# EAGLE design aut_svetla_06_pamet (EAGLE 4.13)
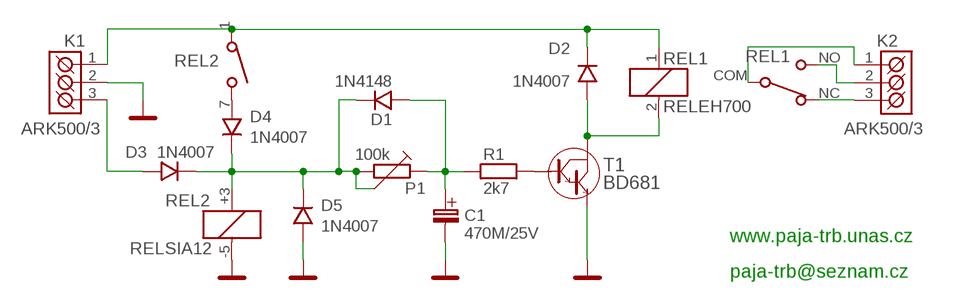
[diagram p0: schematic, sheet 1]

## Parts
C1  470M/25V  [C_EL_5]
D1  1N4148  1N4148_SMD_SOD80  [SOD-80]
D2  1N4007  1N4007_SMD_SM-1  [SM-1]
D3  1N4007  1N4007_SMD_SM-1  [SM-1]
D4  1N4007  1N4007_SMD_SM-1  [SM-1]
D5  1N4007  1N4007_SMD_SM-1  [SM-1]
K1  ARK500/3  [ARK500/3]
K2  ARK500/3  [ARK500/3]
P1  100k  PT-6_V-LEZ  [PT6V]
R1  2k7  R_SMD_1206  [1206]
REL1  RELEH700  [RELEH700]
REL2  RELSIA12  RELSIA  [RELSIA]
T1  BD681  BD681_STOJ  [TO-126S]

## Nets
GND: C1.C-(C_EL-) D5.A K1.2(K2) REL2.-5(CIVKA:C-) T1.1(E)
N$1: D2.K K1.1(K1) REL1.1(CIVKA:C1) REL2.1
N$2: C1.C+(C_EL+) D1.A P1.1 R1.1
N$3: D2.A REL1.2(CIVKA:C2) T1.2(C)
N$4: K2.2(K2) REL1.NO(PREP:NO)
N$5: K2.3(K3) REL1.NC(PREP:NC)
N$6: K2.1(K1) REL1.COM(PREP:COM)
N$7: R1.2 T1.3(B)
N$8: D4.A REL2.7
N$9: D1.K D3.K D4.K D5.K P1.2 P1.3 REL2.+3(CIVKA:C+)
N$10: D3.A K1.3(K3)

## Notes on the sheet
- www.paja-trb.unas.cz
- paja-trb@seznam.cz

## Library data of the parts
C1 = #PaJa_C-el:470M/25V
D1 = #PaJa_17:1N4148: Univerzalni dioda - 0,15A, 75V
D2 = #PaJa_17:1N4007: Usmernovaci dioda - 1A, 1000V
D3-D5 = #PaJa_18:1N4007: Usmernovaci dioda - 1A, 1000V
K1 K2 = #PaJa_17:ARK500/3: Svorkovnice - roztec 5mm - trojita
P1 = #PaJa_18:PT-6: Trimr PT6 - 6,3mm
R1 = #PaJa_17:R: Rezistor
REL1 = #PaJa_18:RELEH700
REL2 = #PaJa_18:RELSIA??: RELE - 1x spinaci, 5V, 12V, 24V max. spinany proud = 0,5A
T1 = #PaJa_17:BD681

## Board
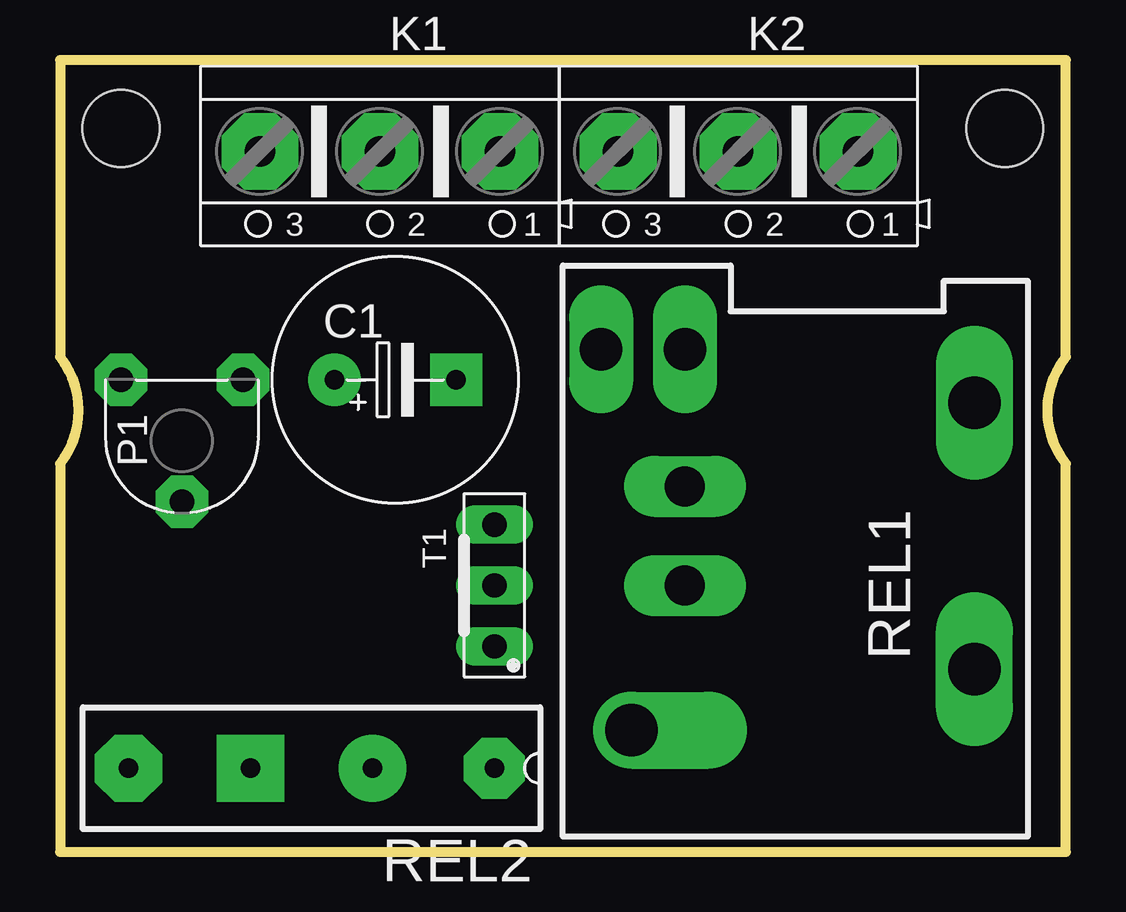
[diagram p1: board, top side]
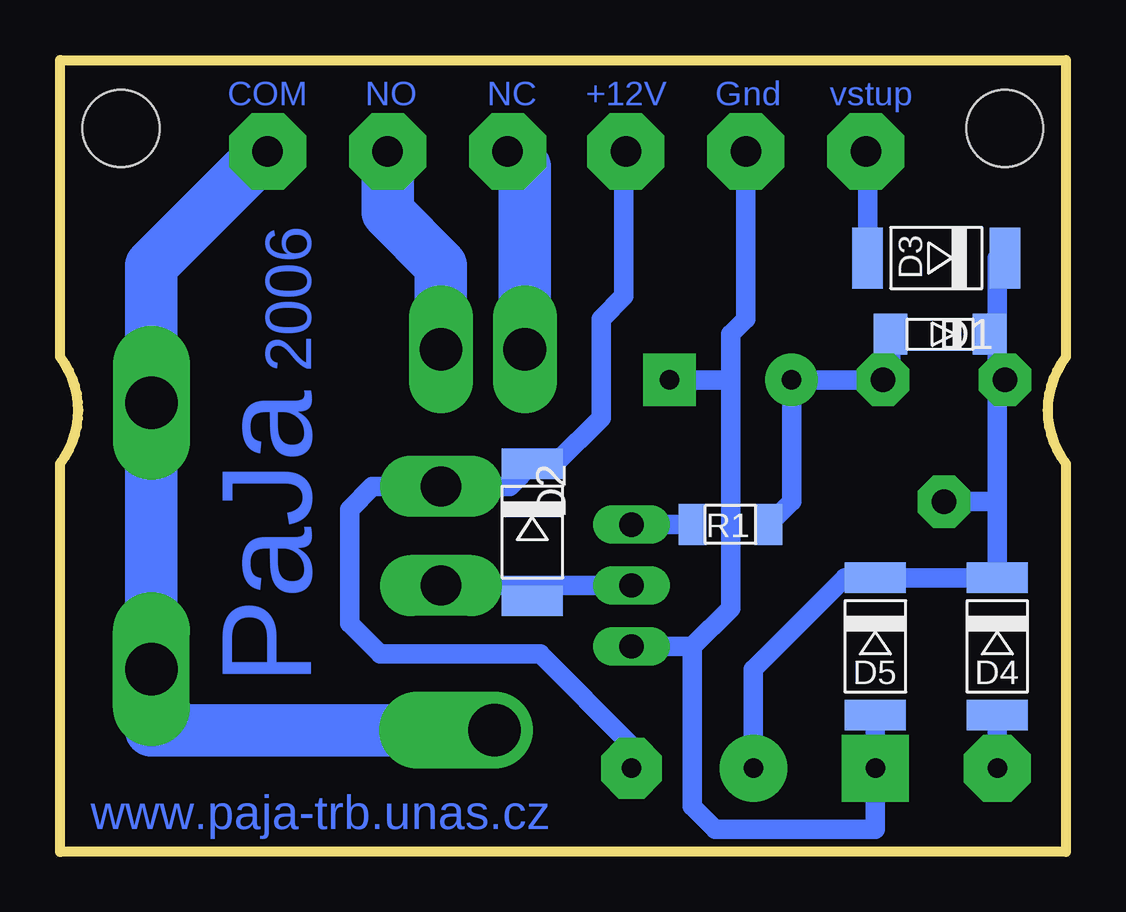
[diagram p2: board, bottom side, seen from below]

Size 41.91 x 33.02 mm. Coordinates in mm from the lower left corner, seen from the top.
Outline: 41.9,0 0,0 0,16.19 arc76 0,20.64 0,33.01 41.9,33.01
Outline: 41.91,0 41.91,16.19 arc-76 41.91,20.64 41.91,33.02
Copper layers (1*16): Top 0.035mm / dielectric 1.5mm / Bottom 0.035mm
Design rules "default": minimum track width 10mil, minimum drill 24mil, track to track 8mil, track to pad 8mil, pad to pad 8mil, via to via 8mil, smd to smd 8mil, copper to edge 40mil, drill to drill 8mil, minimum pad ring 10mil, minimum via ring 8mil, stop-mask expansion 4mil, vias tented up to drill 0mil, thermal gap 10mil
Holes 3.2 mm at 2.54,30.16 39.37,30.16

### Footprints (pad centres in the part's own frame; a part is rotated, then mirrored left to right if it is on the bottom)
C_EL_5 = drill 0.813 pad 2.184 round: C+ -2.54,0 | drill 0.813 pad 2.184 square: C- 2.54,0
SOD-80 = smd 1.397 x 1.702: A 1.905,0; K -2.223,0
SM-1 = smd 1.27 x 2.54: A 2.54,0; K -3.175,0
ARK500/3 = drill 1.27 pad 3.2 octagon: 1 -5,0; 2 0,0; 3 5,0
PT6V = drill 1.016 pad 2.184 octagon: 1 -2.54,-2.54; 2 2.54,-2.54; 3 0,2.54
1206 = smd 1.143 x 1.702: 1 -1.587,0; 2 1.587,0
RELEH700 = drill 1.676 pad 2.54 long: 1 -2.857,-4.763; 2 1.27,-4.763 | drill 2.184 pad 3.2 long: COM -6.35,7.303; COM1 4.763,7.303 | drill 2.184 pad 3.2 offset: COM2 7.303,-6.985 | drill 1.778 pad 2.54 long: NC -8.572,-8.255; NO -8.572,-4.763
RELSIA = drill 0.813 pad 2.54 octagon: 1 -7.62,0 | drill 0.813 pad 2.8 octagon: 7 7.62,0 | drill 0.813 pad 2.8 round: +3 -2.54,0 | drill 0.813 pad 2.8 square: -5 2.54,0
TO-126S = drill 1.016 pad 1.6 long: 1 -2.54,0; 2 0,0; 3 2.54,0

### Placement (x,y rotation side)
C1  13.97,19.68 0 top
D1  5.4,21.59 180 bottom
D2  22.23,13.02 270 bottom
D3  5.71,24.77 180 bottom
D4  2.86,8.26 270 bottom
D5  7.94,8.26 270 bottom
K1  13.34,29.21 180 top
K2  28.26,29.21 180 top
P1  5.08,17.14 180 top
R1  13.97,13.65 180 bottom
REL1  30.8,12.38 270 top
REL2  10.48,3.49 180 top
T1  18.1,11.11 90 top

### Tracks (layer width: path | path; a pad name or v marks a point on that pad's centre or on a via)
GND
  Bottom 0.813: K1.2 13.34,22.23 13.97,21.59 13.97,19.68 | 13.97,19.68 13.97,10.16 15.56,8.57 | 15.56,8.57 T1.1 | 13.97,19.68 C1.C- | 15.56,8.57 15.56,1.91 14.61,0.95 7.94,0.95 REL2.-5 D5.A
N$1
  Bottom 0.813: K1.1 18.41,29.21 18.41,23.18 19.37,22.23 19.37,18.1 21.27,16.19 D2.K 23.18,15.24 REL1.1 28.89,15.24 29.84,14.29 29.84,9.53 28.57,8.26 21.91,8.26 18.1,4.45 REL2.1
N$2
  Bottom 0.813: D1.A 7.3,20 P1.1 C1.C+ 11.43,14.61 R1.1
N$3
  Bottom 0.813: T1.2 22.23,11.11 | 22.23,11.11 D2.A | 22.23,11.11 REL1.2
N$4
  Bottom 2.184: K2.2 28.26,26.67 26.04,24.45 REL1.NO
N$5
  Bottom 1.778: 23.18,29.21 K2.3
  Bottom 2.184: 23.18,29.21 22.54,28.57 REL1.NC
N$6
  Bottom 1.778: 38.1,19.05 REL1.COM
  Bottom 1.93: 33.34,29.21 K2.1
  Bottom 2.184: 33.34,29.21 38.1,24.45 38.1,19.05 | REL1.COM 38.1,5.08 26.04,5.08
N$7
  Bottom 0.813: R1.2 T1.3
N$8
  Bottom 0.813: REL2.7 D4.A
N$9
  Bottom 0.813: REL2.+3 13.02,7.62 9.21,11.43 D5.K D4.K 2.86,14.61 | 2.86,14.61 P1.3 | 2.86,14.61 2.86,19.68 | D3.K 2.86,24.77 2.86,21.59 | 2.86,19.68 P1.2 | 2.86,19.68 2.86,21.59 | 2.86,21.59 D1.K
N$10
  Bottom 0.813: K1.3 8.26,29.21 D3.A

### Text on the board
Bottom: vstup | Gnd | +12V | NC | NO | COM | 2006 | PaJa | www.paja-trb.unas.cz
